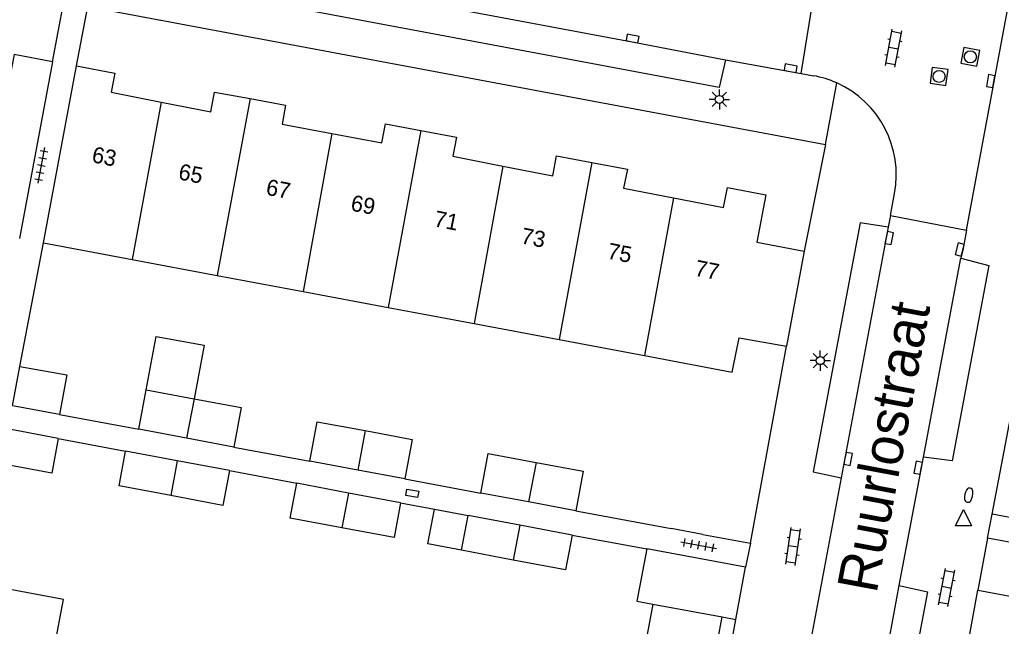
# Model space of a CAD drawing. Extents: x 124000 to 128010, y 398999 to 403000.
# Drawn here: x 126636.3 to 126697.3, y 399627.2 to 399664.9 of the extents above; entities that cross this region are included whole.
import ezdxf

# ---------------------------------------------------------------- set-up
doc = ezdxf.new("R2010")
doc.units = 0
for name, color, linetype in [('gg-afsc-erfafscheiding', 7, 'Continuous'), ('gg-afsc-muur', 7, 'Continuous'), ('gg-anno-huisnummerreeks BGT', 7, 'Continuous'), ('gg-anno-openbare ruimte label', 7, 'Continuous'), ('gg-bbg-bijgebouw', 7, 'Continuous'), ('gg-bbg-gedigitaliseerde bebouwing', 7, 'Continuous'), ('gg-bbg-gedigitaliseerde bijgebouw', 7, 'Continuous'), ('gg-bbg-hoofdgebouw', 7, 'Continuous'), ('gg-bbg-luifel en loopbrug', 7, 'Continuous'), ('gg-bbg-tussenscheiding', 7, 'Continuous'), ('gg-knt-verharding', 7, 'Continuous'), ('gg-knt-verharding nz', 7, 'Continuous'), ('gt-grn-weggrens', 7, 'Continuous'), ('gt-symb-brandkraan', 7, 'Continuous'), ('gt-symb-klinker verharding', 7, 'Continuous'), ('gt-symb-kolk', 7, 'Continuous'), ('gt-symb-kolk center center', 7, 'Continuous'), ('gt-symb-lichtmast', 7, 'Continuous'), ('gt-symb-rioolschacht', 7, 'Continuous'), ('gt-symb-tegel verharding', 7, 'Continuous'), ('gt-symb-waterafsluiter', 7, 'Continuous')]:
    doc.layers.add(name, color=color, linetype=linetype)

# ---------------------------------------------------------------- blocks, each defined once
blk = doc.blocks.new('gt0-RS')
at = {"layer": 'gt-symb-rioolschacht'}
blk.add_lwpolyline([(-0.5, -0.5), (0.5, -0.5), (0.5, 0.5), (-0.5, 0.5)], close=True, dxfattribs=at)
blk.add_circle((0, 0), 0.375, dxfattribs=at)
blk = doc.blocks.new('gt0-KOLK')
at = {"layer": 'gt-symb-kolk'}
blk.add_lwpolyline([(0, 0), (0.375, 0), (0.375, 0.4), (-0.375, 0.4), (-0.375, 0), (0, 0)], dxfattribs=at)
blk = doc.blocks.new('gt0-KL1')
at = {"layer": 'gt-symb-klinker verharding'}
for p, q in [((-1.15, 0.3), (1.15, 0.3)), ((-1, -0.3), (-1, 0.3)), ((-0.5, 0.3), (-0.5, 0.45)), ((0, -0.3), (0, 0.3)), ((0.5, 0.3), (0.5, 0.45)), ((1, -0.3), (1, 0.3)), ((-1.15, -0.3), (1.15, -0.3)), ((-0.5, -0.45), (-0.5, -0.3)), ((0.5, -0.45), (0.5, -0.3))]:
    blk.add_line(p, q, dxfattribs=at)
blk = doc.blocks.new('gt0-WAFSL')
at = {"layer": 'gt-symb-waterafsluiter'}
for p, q in [((-0.5, -0.333), (0, 0.667)), ((0, 0.667), (0.5, -0.333)), ((0.5, -0.333), (-0.5, -0.333))]:
    blk.add_line(p, q, dxfattribs=at)
blk = doc.blocks.new('gt0-BR')
at = {"layer": 'gt-symb-brandkraan'}
for centre, radius, start, end in [((-0.244, 0), 0.206, 107.56694, 252.43307), ((0.599, -2.664), 3, 106.89205, 107.56694), ((0, -0.691), 0.938, 73.10799, 106.89205), ((-0.599, -2.664), 3, 72.43309, 73.10799), ((0.244, 0), 0.206, 287.56695, 72.43309), ((0.599, 2.664), 3, 252.43307, 253.10797), ((0, 0.691), 0.938, 253.10797, 286.89206), ((-0.599, 2.664), 3, 286.89206, 287.56695)]:
    blk.add_arc(centre, radius, start, end, dxfattribs=at)
blk = doc.blocks.new('gt0-TEG1')
at = {"layer": 'gt-symb-tegel verharding'}
for p, q in [((-1.125, 0), (1.125, 0)), ((-0.9, -0.25), (-0.9, 0.25)), ((-0.45, -0.25), (-0.45, 0.25)), ((0, -0.25), (0, 0.25)), ((0.45, -0.25), (0.45, 0.25)), ((0.9, -0.25), (0.9, 0.25))]:
    blk.add_line(p, q, dxfattribs=at)
blk = doc.blocks.new('gt0-LMAST')
at = {"layer": 'gt-symb-lichtmast'}
for p, q in [((-0.005, 0.246), (-0.005, 0.621)), ((-0.182, 0.173), (-0.447, 0.438)), ((0.172, 0.173), (0.437, 0.438)), ((-0.255, -0.004), (-0.63, -0.004)), ((-0.182, -0.181), (-0.447, -0.446)), ((-0.005, -0.254), (-0.005, -0.629)), ((0.437, -0.446), (0.172, -0.181)), ((0.245, -0.004), (0.62, -0.004))]:
    blk.add_line(p, q, dxfattribs=at)
blk.add_circle((-0.005, -0.004), 0.25, dxfattribs=at)
blk = doc.blocks.new('gt0-KOLKCC')
at = {"layer": 'gt-symb-kolk center center'}
blk.add_lwpolyline([(-0.375, 0.2), (0.375, 0.2), (0.375, -0.2), (-0.375, -0.2)], close=True, dxfattribs=at)

msp = doc.modelspace()

# ---------------------------------------------------------------- linework, layer by layer
at = {"layer": 'gg-afsc-erfafscheiding'}
for p, q in [((126638.758, 399640.373), (126643.692, 399639.453)), ((126638.689, 399638.886), (126642.874, 399638.099)), ((126649.599, 399638.352), (126654.326, 399637.47)), ((126649.328, 399636.884), (126653.512, 399636.096)), ((126660.223, 399636.37), (126664.94, 399635.491)), ((126659.966, 399634.882), (126662.063, 399634.487)), ((126670.847, 399634.389), (126676.78, 399633.281)), ((126670.614, 399632.878), (126675.266, 399632.017))]:
    msp.add_line(p, q, dxfattribs=at)
at = {"layer": 'gg-afsc-muur'}
for p, q in [((126636.306, 399643.364), (126637.771, 399651.041)), ((126681.698, 399632.38), (126683.94, 399644.619)), ((126678.747, 399632.921), (126676.78, 399633.281)), ((126678.747, 399632.921), (126681.698, 399632.38)), ((126693.945, 399619.15), (126695.841, 399629.445)), ((126679.651, 399621.275), (126680.797, 399627.637))]:
    msp.add_line(p, q, dxfattribs=at)
at = {"layer": 'gg-bbg-bijgebouw'}
for p, q in [((126638.689, 399638.886), (126635.441, 399639.497)), ((126646.085, 399637.494), (126642.874, 399638.099)), ((126649.328, 399636.884), (126646.085, 399637.494)), ((126656.718, 399635.493), (126653.512, 399636.096)), ((126659.966, 399634.882), (126656.718, 399635.493)), ((126667.372, 399633.488), (126664.16, 399634.092)), ((126670.614, 399632.878), (126667.372, 399633.488)), ((126696.442, 399632.687), (126695.841, 399629.445)), ((126702.599, 399631.554), (126696.442, 399632.687)), ((126681.401, 399630.879), (126675.266, 399632.017)), ((126680.797, 399627.637), (126681.401, 399630.879)), ((126675.636, 399628.583), (126679.954, 399627.792)), ((126679.954, 399627.792), (126680.797, 399627.637))]:
    msp.add_line(p, q, dxfattribs=at)
for points in [[(126675.266, 399632.017), (126674.648, 399628.764), (126675.636, 399628.583)], [(126695.841, 399629.445), (126701.99, 399628.317), (126702.599, 399631.554)]]:
    msp.add_lwpolyline(points, dxfattribs=at)
at = {"layer": 'gg-bbg-gedigitaliseerde bebouwing'}
msp.add_lwpolyline([(126638.458, 399625.934), (126639.01, 399628.883), (126633.702, 399629.877), (126633.15, 399626.928)], dxfattribs=at)
at = {"layer": 'gg-bbg-gedigitaliseerde bijgebouw'}
for p, q in [((126643.692, 399639.453), (126644.15, 399641.91)), ((126644.15, 399641.91), (126647.127, 399641.355)), ((126646.666, 399638.899), (126643.692, 399639.453)), ((126649.599, 399638.352), (126646.666, 399638.899)), ((126657.303, 399636.915), (126654.326, 399637.47)), ((126660.223, 399636.37), (126657.303, 399636.915)), ((126667.919, 399634.935), (126664.94, 399635.491)), ((126670.847, 399634.389), (126667.919, 399634.935)), ((126663.754, 399631.931), (126664.16, 399634.092)), ((126666.962, 399631.327), (126663.754, 399631.931))]:
    msp.add_line(p, q, dxfattribs=at)
for points in [[(126638.758, 399640.373), (126635.849, 399640.915), (126636.306, 399643.364)], [(126636.306, 399643.364), (126639.216, 399642.83), (126638.758, 399640.373)], [(126647.127, 399641.355), (126650.057, 399640.809), (126649.599, 399638.352)], [(126654.326, 399637.47), (126654.784, 399639.927), (126657.764, 399639.371)], [(126657.764, 399639.371), (126660.681, 399638.827), (126660.223, 399636.37)], [(126638.689, 399638.886), (126638.283, 399636.725), (126635.047, 399637.334)], [(126645.686, 399635.332), (126642.467, 399635.938), (126642.874, 399638.099)], [(126664.94, 399635.491), (126665.399, 399637.948), (126668.38, 399637.392)], [(126668.38, 399637.392), (126671.305, 399636.846), (126670.847, 399634.389)], [(126649.328, 399636.884), (126648.921, 399634.723), (126645.686, 399635.332)], [(126656.315, 399633.331), (126653.106, 399633.935), (126653.512, 399636.096)], [(126659.966, 399634.882), (126659.559, 399632.721), (126656.315, 399633.331)], [(126670.614, 399632.878), (126670.207, 399630.717), (126666.962, 399631.327)]]:
    msp.add_lwpolyline(points, dxfattribs=at)
at = {"layer": 'gg-bbg-hoofdgebouw'}
for p, q in [((126638.338, 399662.303), (126636.276, 399651.305)), ((126637.771, 399651.041), (126639.831, 399662.04)), ((126637.771, 399651.041), (126643.277, 399650.008)), ((126643.277, 399650.008), (126648.566, 399649.017)), ((126685.042, 399650.524), (126683.94, 399644.619)), ((126648.566, 399649.017), (126653.913, 399648.014)), ((126653.913, 399648.014), (126659.201, 399647.022)), ((126659.201, 399647.022), (126664.528, 399646.023)), ((126664.528, 399646.023), (126669.815, 399645.032)), ((126669.815, 399645.032), (126675.123, 399644.036))]:
    msp.add_line(p, q, dxfattribs=at)
for points in [[(126638.338, 399662.303), (126635.952, 399662.758), (126635.727, 399661.579), (126632.624, 399662.162)], [(126639.831, 399662.04), (126642.204, 399661.585), (126641.982, 399660.408), (126645.077, 399659.795)], [(126645.077, 399659.795), (126648.173, 399659.182), (126648.403, 399660.421), (126650.606, 399660.012)], [(126650.606, 399660.012), (126652.811, 399659.603), (126652.598, 399658.421), (126655.697, 399657.842)], [(126655.697, 399657.842), (126658.796, 399657.264), (126659.02, 399658.443), (126661.223, 399658.025)], [(126661.223, 399658.025), (126663.427, 399657.607), (126663.215, 399656.428), (126666.318, 399655.819)], [(126666.318, 399655.819), (126669.42, 399655.21), (126669.649, 399656.449), (126671.853, 399656.041)], [(126671.853, 399656.041), (126674.056, 399655.633), (126673.822, 399654.452), (126676.926, 399653.846)], [(126676.926, 399653.846), (126680.031, 399653.239), (126680.267, 399654.477), (126682.65, 399654.022), (126682.097, 399651.084), (126685.042, 399650.524)], [(126675.123, 399644.036), (126680.568, 399643.015), (126680.997, 399645.148), (126683.94, 399644.619)]]:
    msp.add_lwpolyline(points, dxfattribs=at)
at = {"layer": 'gg-bbg-luifel en loopbrug'}
msp.add_line((126662.063, 399634.487), (126664.16, 399634.092), dxfattribs=at)
for points in [[(126644.15, 399641.91), (126644.773, 399645.232), (126647.75, 399644.674), (126647.127, 399641.355)], [(126663.754, 399631.931), (126661.657, 399632.325), (126662.063, 399634.487)], [(126675.636, 399628.583), (126675.094, 399625.695), (126679.408, 399624.885), (126679.954, 399627.792)]]:
    msp.add_lwpolyline(points, dxfattribs=at)
at = {"layer": 'gg-bbg-tussenscheiding'}
for p, q in [((126645.077, 399659.795), (126643.277, 399650.008)), ((126650.606, 399660.012), (126648.566, 399649.017)), ((126661.223, 399658.025), (126659.201, 399647.022)), ((126655.697, 399657.842), (126653.913, 399648.014)), ((126666.318, 399655.819), (126664.528, 399646.023)), ((126671.853, 399656.041), (126669.815, 399645.032)), ((126676.926, 399653.846), (126675.123, 399644.036)), ((126647.127, 399641.355), (126646.666, 399638.899)), ((126657.764, 399639.371), (126657.303, 399636.915)), ((126646.085, 399637.494), (126645.686, 399635.332)), ((126668.38, 399637.392), (126667.919, 399634.935)), ((126656.718, 399635.493), (126656.315, 399633.331)), ((126667.372, 399633.488), (126666.962, 399631.327))]:
    msp.add_line(p, q, dxfattribs=at)
at = {"layer": 'gg-knt-verharding'}
for p, q in [((126696.722, 399634.17), (126706.826, 399687.639)), ((126684.854, 399661.572), (126685.641, 399666.498)), ((126638.338, 399662.303), (126639.035, 399666.022)), ((126639.831, 399662.04), (126640.525, 399665.743)), ((126640.525, 399665.743), (126686.366, 399657.163)), ((126680.15, 399662.423), (126684.854, 399661.572)), ((126686.366, 399657.163), (126685.042, 399650.524)), ((126690.4, 399652.742), (126690.265, 399652.025)), ((126690.4, 399652.742), (126695.13, 399651.833)), ((126690.949, 399629.743), (126692.46, 399637.724)), ((126687.344, 399636.441), (126685.356, 399625.831)), ((126696.442, 399632.687), (126696.722, 399634.17)), ((126705.182, 399632.601), (126696.722, 399634.17)), ((126681.698, 399632.38), (126681.401, 399630.879))]:
    msp.add_line(p, q, dxfattribs=at)
for points in [[(126680.15, 399662.423), (126679.755, 399660.711), (126641.836, 399667.83), (126642.133, 399669.588)], [(126690.265, 399652.025), (126688.519, 399652.283), (126685.602, 399636.806), (126687.344, 399636.441)], [(126695.13, 399651.833), (126694.898, 399650.584), (126694.772, 399650.1)], [(126694.772, 399650.1), (126696.506, 399649.646), (126694.232, 399637.486), (126692.46, 399637.724)], [(126690.949, 399629.743), (126692.7, 399629.35), (126689.419, 399611.911), (126687.668, 399612.19)]]:
    msp.add_lwpolyline(points, dxfattribs=at)
at = {"layer": 'gg-knt-verharding nz'}
for p, q in [((126695.13, 399651.833), (126698.7, 399671.078)), ((126684.854, 399661.572), (126685.618, 399661.434)), ((126690.4, 399652.742), (126690.658, 399654.114)), ((126690.265, 399652.025), (126687.344, 399636.441)), ((126692.46, 399637.724), (126694.772, 399650.1)), ((126687.668, 399612.19), (126690.949, 399629.743))]:
    msp.add_line(p, q, dxfattribs=at)
msp.add_lwpolyline([(126642.133, 399669.588), (126674.344, 399663.55), (126680.15, 399662.423)], dxfattribs=at)
for centre, radius, start, end in [((126684.512, 399655.309), 6.224, 65.75257, 79.76451), ((126684.504, 399655.271), 6.262, 349.35002, 65.82968)]:
    msp.add_arc(centre, radius, start, end, dxfattribs=at)
at = {"layer": 'gt-grn-weggrens'}
msp.add_line((126686.366, 399657.163), (126687.068, 399660.984), dxfattribs=at)

# ---------------------------------------------------------------- block references
at = {"layer": 'gt-symb-brandkraan', "rotation": 77.29726808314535}
msp.add_blockref('gt0-BR', (126695.266, 399635.358), dxfattribs=at)
at = {"layer": 'gt-symb-klinker verharding'}
for p, rotation in [((126690.597, 399663.142), 79.34163849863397), ((126684.354, 399632.166), 81.72410717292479), ((126693.895, 399629.62), 79.34163849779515)]:
    msp.add_blockref('gt0-KL1', p, dxfattribs=dict(at, rotation=rotation))
at = {"layer": 'gt-symb-kolk'}
for p, rotation in [((126674.344, 399663.55), -10.602058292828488), ((126684.167, 399661.705), -10.140793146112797), ((126696.825, 399661.061), 79.5773454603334), ((126690.133, 399651.38), -101.53462065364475), ((126694.898, 399650.584), 75.40804379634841), ((126687.574, 399637.646), -100.54573436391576), ((126692.317, 399637.027), 79.3416384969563)]:
    msp.add_blockref('gt0-KOLK', p, dxfattribs=dict(at, rotation=rotation))
at = {"layer": 'gt-symb-kolk center center', "rotation": -10.54573436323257}
msp.add_blockref('gt0-KOLKCC', (126660.688, 399635.471), dxfattribs=at)
at = {"layer": 'gt-symb-lichtmast'}
for p in [(126679.774, 399659.967), (126686.048, 399643.727)]:
    msp.add_blockref('gt0-LMAST', p, dxfattribs=at)
at = {"layer": 'gt-symb-rioolschacht'}
for p, rotation in [((126695.365, 399662.611), 79.45426563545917), ((126693.425, 399661.39), 81.89420641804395)]:
    msp.add_blockref('gt0-RS', p, dxfattribs=dict(at, rotation=rotation))
at = {"layer": 'gt-symb-tegel verharding'}
for p, rotation in [((126637.638, 399655.862), -100.60205829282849), ((126678.488, 399632.253), -10.781616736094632)]:
    msp.add_blockref('gt0-TEG1', p, dxfattribs=dict(at, rotation=rotation))
at = {"layer": 'gt-symb-waterafsluiter'}
msp.add_blockref('gt0-WAFSL', (126694.939, 399633.791), dxfattribs=at)

# ---------------------------------------------------------------- texts
at = {"layer": 'gg-anno-huisnummerreeks BGT'}
for s, rotation, p in [('63', 348.8, (126640.727, 399656.069)), ('65', 348.8, (126646.106, 399655.004)), ('67', 349.4, (126651.549, 399654.04)), ('69', 349.5, (126656.816, 399653.055)), ('71', 348.9, (126661.987, 399652.083)), ('73', 348.9, (126667.392, 399651.022)), ('75', 348.9, (126672.757, 399650.076)), ('77', 348.9, (126678.188, 399649.015))]:
    msp.add_text(s, height=1, rotation=rotation, dxfattribs=at).set_placement(p)
at = {"layer": 'gg-anno-openbare ruimte label'}
msp.add_text('Ruurlostraat', height=2.5, rotation=79.4, dxfattribs=at).set_placement((126689.532, 399629.191))

doc.saveas('drawing.dxf')
